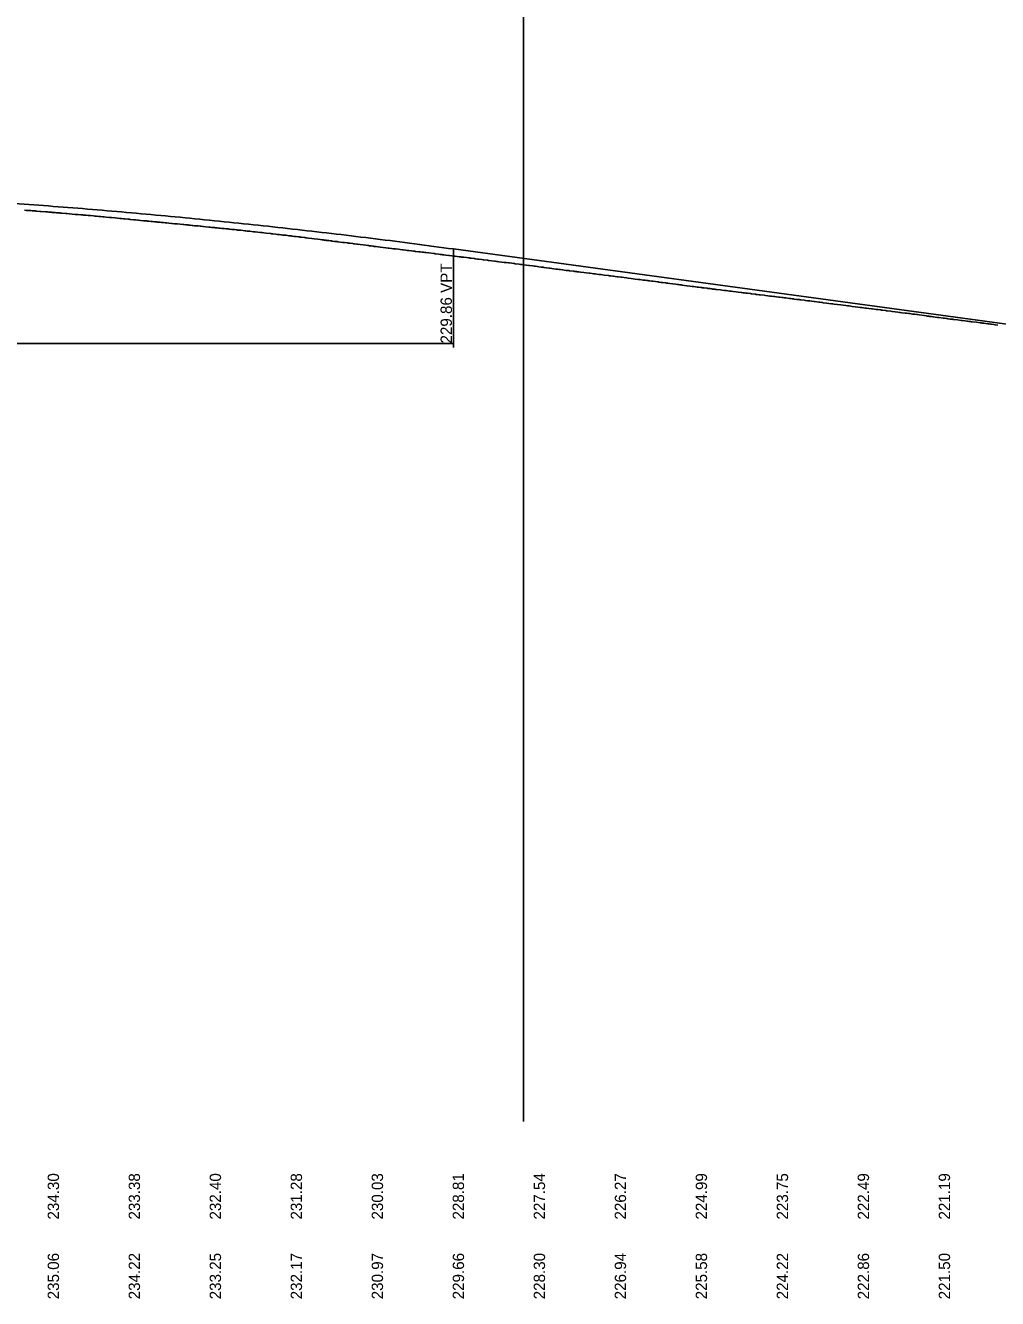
# Model space of a CAD drawing. Extents: x 1838386 to 1955906, y 719739 to 834437.
# Drawn here: x 1890591 to 1891191, y 825634 to 826420 of the extents above; entities that cross this region are included whole.
import ezdxf

# ---------------------------------------------------------------- set-up
doc = ezdxf.new("R2010")
doc.units = 0
for name, color, linetype in [('RD_DDB_Profile_EX', 7, 'Continuous'), ('RD_DDB_Profile_PR', 7, 'Continuous'), ('RD_DDB_StripGrade', 7, 'Continuous'), ('RD_DDB_VCLbl', 7, 'Continuous'), ('RD_Sketch1', 7, 'Continuous')]:
    doc.layers.add(name, color=color, linetype=linetype)

msp = doc.modelspace()

# ---------------------------------------------------------------- linework, layer by layer
at = {"layer": 'RD_DDB_Profile_EX'}
for points in [[(1890590.81, 826306.42), (1890592.08, 826306.29), (1890593.56, 826306.2), (1890594.18, 826306.16), (1890594.75, 826306.1), (1890595.54, 826306.02), (1890597.46, 826305.91), (1890597.94, 826305.87), (1890600.28, 826305.67), (1890601.13, 826305.6), (1890603.9, 826305.36), (1890604.35, 826305.32), (1890604.93, 826305.28), (1890605.81, 826305.2), (1890606.2, 826305.16), (1890607.18, 826305.09), (1890607.83, 826305.02), (1890608.71, 826304.97), (1890609.71, 826304.87), (1890610.45, 826304.81), (1890611.33, 826304.74), (1890612.52, 826304.65), (1890613.17, 826304.59), (1890613.74, 826304.54), (1890616.29, 826304.33), (1890616.97, 826304.27), (1890618.48, 826304.11), (1890620.11, 826304.01), (1890621.99, 826303.8), (1890622.39, 826303.78), (1890623.46, 826303.72), (1890623.95, 826303.68)], [(1890623.95, 826303.68), (1890625.44, 826303.51), (1890626.89, 826303.43), (1890627.24, 826303.4), (1890627.61, 826303.37), (1890627.92, 826303.33), (1890628.9, 826303.22), (1890630.1, 826303.13), (1890630.79, 826303.06), (1890631.54, 826303.01), (1890633.44, 826302.83), (1890634.25, 826302.74), (1890635.25, 826302.67), (1890636.61, 826302.54), (1890637.72, 826302.42), (1890639.11, 826302.32), (1890639.93, 826302.24), (1890641.2, 826302.09), (1890643.15, 826301.95), (1890644.19, 826301.86), (1890644.5, 826301.83), (1890646.76, 826301.61), (1890649.54, 826301.35), (1890650.02, 826301.3), (1890650.6, 826301.25), (1890651.86, 826301.1), (1890652.78, 826301.03), (1890654.47, 826300.87), (1890655.55, 826300.76), (1890656.05, 826300.72), (1890658.29, 826300.5), (1890658.8, 826300.44), (1890659.28, 826300.4), (1890660.63, 826300.24), (1890661.08, 826300.21), (1890662.42, 826300.1), (1890664.17, 826299.89), (1890665.65, 826299.78), (1890666.03, 826299.74), (1890666.6, 826299.67), (1890667.64, 826299.54), (1890668.98, 826299.45), (1890669.84, 826299.37), (1890671.11, 826299.22), (1890672.27, 826299.13), (1890672.92, 826299.06), (1890673.63, 826299), (1890674.58, 826298.89), (1890675.43, 826298.82), (1890676.47, 826298.7), (1890677.66, 826298.62), (1890678.13, 826298.57), (1890678.6, 826298.52), (1890679.95, 826298.36), (1890681.43, 826298.25), (1890681.88, 826298.21), (1890683.43, 826298.02), (1890685.22, 826297.89), (1890686.91, 826297.68), (1890688.76, 826297.54), (1890689.12, 826297.5), (1890690.4, 826297.35), (1890691.58, 826297.25), (1890692.3, 826297.17), (1890693.09, 826297.11), (1890694.24, 826296.99), (1890694.73, 826296.94), (1890695.78, 826296.81), (1890697, 826296.72), (1890697.92, 826296.63), (1890699.27, 826296.46), (1890699.76, 826296.43), (1890700.75, 826296.35), (1890701.24, 826296.3), (1890702.76, 826296.11), (1890704.63, 826295.98), (1890705.29, 826295.9), (1890706.26, 826295.77), (1890707.66, 826295.66), (1890708.1, 826295.62), (1890708.57, 826295.58), (1890709.75, 826295.43), (1890710.82, 826295.35), (1890711.63, 826295.26), (1890712.53, 826295.18), (1890713.28, 826295.09), (1890713.96, 826295.03), (1890715.16, 826294.89), (1890716.49, 826294.78), (1890717.11, 826294.72), (1890718.67, 826294.51), (1890720.43, 826294.37), (1890721.87, 826294.18), (1890722.18, 826294.13), (1890723.51, 826294.03), (1890724.34, 826293.95), (1890725.69, 826293.78), (1890726.71, 826293.69), (1890727.4, 826293.62), (1890728.24, 826293.53), (1890729.2, 826293.41)], [(1890729.2, 826293.41), (1890729.93, 826293.34), (1890732.16, 826293.11), (1890733.13, 826293), (1890736.34, 826292.66), (1890737.52, 826292.54), (1890738.45, 826292.43), (1890739.99, 826292.26), (1890742.74, 826291.93), (1890743.26, 826291.87), (1890743.98, 826291.79), (1890745.93, 826291.56), (1890746.79, 826291.45), (1890747.89, 826291.34), (1890749.09, 826291.2), (1890749.5, 826291.15), (1890750.31, 826291.04), (1890751.89, 826290.9), (1890752.2, 826290.86), (1890753.84, 826290.64), (1890755.03, 826290.52), (1890755.33, 826290.5), (1890755.89, 826290.43), (1890757.37, 826290.21), (1890758.5, 826290.1), (1890759.85, 826289.95), (1890760.56, 826289.85), (1890760.89, 826289.8), (1890761.69, 826289.71), (1890763.8, 826289.44), (1890764.42, 826289.36), (1890764.89, 826289.29), (1890766.08, 826289.14), (1890768.11, 826288.89), (1890769.66, 826288.65), (1890771.74, 826288.43), (1890773.18, 826288.23), (1890774.44, 826288.09), (1890775.03, 826288.02), (1890775.73, 826287.94), (1890776.7, 826287.8), (1890777.14, 826287.75), (1890777.54, 826287.71), (1890778.52, 826287.58), (1890779.67, 826287.47), (1890780.2, 826287.4), (1890780.63, 826287.35), (1890782.05, 826287.13), (1890782.66, 826287.07), (1890783.78, 826286.97), (1890784.11, 826286.93), (1890787.29, 826286.51), (1890787.68, 826286.46), (1890788.19, 826286.4), (1890790.21, 826286.13), (1890790.84, 826286.04), (1890791.71, 826285.95), (1890793.34, 826285.74), (1890793.72, 826285.69), (1890794.4, 826285.59), (1890795.8, 826285.44), (1890796.38, 826285.37), (1890797.92, 826285.14), (1890799.77, 826284.95), (1890801.46, 826284.7), (1890802.71, 826284.57), (1890803.15, 826284.51), (1890803.74, 826284.45), (1890804.77, 826284.32), (1890805.93, 826284.17), (1890806.7, 826284.05), (1890807.76, 826283.95), (1890809.08, 826283.79), (1890810.3, 826283.6), (1890812.06, 826283.42), (1890813.79, 826283.16), (1890815.19, 826283.02), (1890815.9, 826282.93), (1890817.34, 826282.73), (1890818.42, 826282.61), (1890819.04, 826282.53), (1890819.87, 826282.45), (1890821.62, 826282.24), (1890822.6, 826282.09), (1890824, 826281.95), (1890824.65, 826281.87), (1890826.15, 826281.66), (1890826.88, 826281.58), (1890827.69, 826281.5), (1890828.08, 826281.45), (1890829.69, 826281.23), (1890830.9, 826281.1), (1890831.4, 826281.04), (1890832.06, 826280.97), (1890832.41, 826280.93), (1890834.12, 826280.72), (1890834.96, 826280.6), (1890836.22, 826280.48), (1890836.72, 826280.41), (1890837.13, 826280.37), (1890837.93, 826280.25)], [(1890837.93, 826280.25), (1890838.5, 826280.17), (1890840.27, 826280), (1890843.46, 826279.59), (1890843.77, 826279.54), (1890844.28, 826279.49), (1890846.6, 826279.2), (1890847.35, 826279.1), (1890848.46, 826278.99), (1890849.08, 826278.91), (1890849.57, 826278.85), (1890850.87, 826278.66), (1890852.64, 826278.47), (1890853.19, 826278.4), (1890854.51, 826278.23), (1890856.17, 826278.01), (1890856.6, 826277.97), (1890857.91, 826277.79), (1890858.99, 826277.67), (1890859.71, 826277.57), (1890860.04, 826277.54), (1890860.69, 826277.47), (1890861.43, 826277.38), (1890861.95, 826277.31), (1890865.14, 826276.92), (1890865.57, 826276.86), (1890866.44, 826276.75), (1890868.56, 826276.47), (1890868.89, 826276.43), (1890870.29, 826276.24), (1890871.29, 826276.12), (1890873.04, 826275.9), (1890873.83, 826275.8), (1890874.39, 826275.73), (1890876.62, 826275.46), (1890877.15, 826275.4), (1890877.63, 826275.34), (1890879.14, 826275.11), (1890880.91, 826274.91), (1890881.27, 826274.87), (1890882.15, 826274.75), (1890882.68, 826274.68), (1890883.65, 826274.57), (1890885.43, 826274.36), (1890886.88, 826274.18), (1890887.67, 826274.06), (1890887.99, 826274.01), (1890889.59, 826273.85), (1890889.89, 826273.81), (1890891.53, 826273.59), (1890892.9, 826273.43), (1890893.2, 826273.4), (1890893.72, 826273.33), (1890896.14, 826273.03), (1890896.86, 826272.92), (1890897.94, 826272.8), (1890898.73, 826272.7), (1890899.11, 826272.65), (1890900.39, 826272.46), (1890902.15, 826272.26), (1890902.55, 826272.21), (1890904.25, 826271.99), (1890905.4, 826271.84), (1890905.73, 826271.79), (1890906.24, 826271.74), (1890907.46, 826271.58), (1890908.33, 826271.46), (1890909.78, 826271.27), (1890910.39, 826271.19), (1890910.99, 826271.11), (1890911.41, 826271.05), (1890914.62, 826270.63), (1890915.31, 826270.53), (1890916.32, 826270.38), (1890917.5, 826270.23), (1890918.82, 826270.06), (1890919.87, 826269.92), (1890920.83, 826269.8), (1890921.62, 826269.67), (1890922.89, 826269.53), (1890923.81, 826269.41), (1890925.17, 826269.22), (1890926.36, 826269.09), (1890926.7, 826269.05), (1890927.2, 826268.99), (1890929.93, 826268.64), (1890930.51, 826268.56), (1890931.41, 826268.46), (1890931.89, 826268.4), (1890932.26, 826268.35), (1890932.87, 826268.28), (1890934.04, 826268.11), (1890935.96, 826267.91), (1890937.41, 826267.73), (1890939.36, 826267.48), (1890939.72, 826267.44), (1890941.11, 826267.25), (1890942, 826267.14), (1890942.94, 826267.03), (1890944.02, 826266.9), (1890945.23, 826266.75)], [(1890945.23, 826266.75), (1890946.47, 826266.58), (1890948.47, 826266.35), (1890951.26, 826265.98), (1890951.77, 826265.9), (1890952.48, 826265.82), (1890953.99, 826265.63), (1890954.34, 826265.59), (1890955.32, 826265.45), (1890956.72, 826265.3), (1890957.27, 826265.23), (1890959.05, 826265.01), (1890959.52, 826264.95), (1890960.94, 826264.77), (1890962.41, 826264.56), (1890963.35, 826264.45), (1890965.26, 826264.21), (1890966.56, 826264.05), (1890967.76, 826263.87), (1890969.61, 826263.66), (1890970.58, 826263.53), (1890972.6, 826263.27), (1890973.08, 826263.2), (1890973.81, 826263.11), (1890974.84, 826262.97), (1890975.57, 826262.87), (1890976.1, 826262.8), (1890976.63, 826262.72), (1890978.07, 826262.56), (1890978.63, 826262.48), (1890980.17, 826262.27), (1890981.95, 826262.05), (1890982.33, 826262), (1890983.72, 826261.81), (1890984.67, 826261.69), (1890986.61, 826261.45), (1890987.16, 826261.38), (1890987.77, 826261.3), (1890989.05, 826261.11), (1890990.94, 826260.88), (1890992.68, 826260.66), (1890993.85, 826260.51), (1890994.39, 826260.43), (1890995.2, 826260.34), (1890996.14, 826260.2), (1890996.76, 826260.13), (1890998.21, 826259.94), (1890999.5, 826259.77), (1890999.89, 826259.72), (1891001.48, 826259.5), (1891002.81, 826259.34), (1891003.86, 826259.21), (1891005.91, 826258.95), (1891006.83, 826258.83), (1891008.19, 826258.68), (1891008.87, 826258.59), (1891009.26, 826258.53), (1891010.38, 826258.37), (1891012.17, 826258.17), (1891012.54, 826258.13), (1891013.95, 826257.94), (1891014.94, 826257.82), (1891015.73, 826257.71), (1891016.93, 826257.58), (1891017.5, 826257.51), (1891017.88, 826257.46), (1891020.46, 826257.15), (1891021.23, 826257.05), (1891022.85, 826256.84), (1891023.88, 826256.72), (1891025.84, 826256.47), (1891027.04, 826256.32), (1891028.18, 826256.16), (1891030.01, 826255.96), (1891031.37, 826255.79), (1891033.05, 826255.57), (1891033.52, 826255.51), (1891034.27, 826255.43), (1891035.29, 826255.29), (1891035.95, 826255.21), (1891037.08, 826255.05), (1891038.97, 826254.84), (1891039.58, 826254.77), (1891042.03, 826254.46), (1891042.45, 826254.4), (1891043.1, 826254.33), (1891044.21, 826254.18), (1891044.91, 826254.1), (1891047.42, 826253.81), (1891048.05, 826253.73), (1891049.55, 826253.52), (1891050.92, 826253.37), (1891051.86, 826253.26), (1891053.12, 826253.09), (1891053.48, 826253.05), (1891053.97, 826252.99), (1891054.91, 826252.86), (1891056.28, 826252.72), (1891057.01, 826252.63), (1891058.47, 826252.44), (1891059, 826252.38)], [(1891059, 826252.38), (1891059.89, 826252.28), (1891060.73, 826252.18), (1891063, 826251.88), (1891063.81, 826251.77), (1891064.53, 826251.69), (1891065.08, 826251.64), (1891065.59, 826251.58), (1891065.92, 826251.54), (1891067.39, 826251.33), (1891068.87, 826251.16), (1891069.59, 826251.07), (1891070.06, 826251.01), (1891071.96, 826250.76), (1891072.74, 826250.65), (1891073.98, 826250.51), (1891074.51, 826250.44), (1891074.83, 826250.4), (1891075.58, 826250.31), (1891076.63, 826250.18), (1891078.09, 826249.99), (1891078.42, 826249.95), (1891081.11, 826249.59), (1891081.67, 826249.51), (1891082.92, 826249.38), (1891083.44, 826249.32), (1891083.76, 826249.28), (1891085.74, 826249.02), (1891087.29, 826248.82), (1891088.79, 826248.61), (1891089.8, 826248.49), (1891090.6, 826248.37), (1891092.37, 826248.17), (1891092.68, 826248.13), (1891094.73, 826247.87), (1891096.19, 826247.68), (1891097.72, 826247.47), (1891098.7, 826247.35), (1891099.53, 826247.23), (1891100.85, 826247.08), (1891101.6, 826246.99), (1891103.48, 826246.76), (1891105.17, 826246.55), (1891106.66, 826246.35), (1891107.61, 826246.25), (1891108.74, 826246.09), (1891109.83, 826245.97), (1891110.5, 826245.88), (1891112.01, 826245.69), (1891113.81, 826245.46), (1891114.27, 826245.41), (1891116.51, 826245.12), (1891117.4, 826244.99), (1891118.84, 826244.83), (1891119.39, 826244.76), (1891119.8, 826244.71), (1891120.47, 826244.63), (1891122.41, 826244.38), (1891122.76, 826244.33), (1891123.3, 826244.27), (1891125.41, 826243.99), (1891126.34, 826243.85), (1891128.28, 826243.63), (1891129.91, 826243.4), (1891130.85, 826243.29), (1891131.23, 826243.25), (1891132.4, 826243.1), (1891134.27, 826242.85), (1891135.28, 826242.7), (1891136.38, 826242.58), (1891137.18, 826242.49), (1891138.87, 826242.27), (1891140.07, 826242.12), (1891141.5, 826241.94), (1891141.91, 826241.89), (1891143.08, 826241.74), (1891146.07, 826241.32), (1891147.43, 826241.1), (1891147.82, 826241.04), (1891148.95, 826240.89), (1891149.61, 826240.78), (1891150.69, 826240.68), (1891151.41, 826240.59), (1891151.85, 826240.54), (1891152.96, 826240.39), (1891154.3, 826240.22), (1891155.15, 826240.11), (1891157.83, 826239.76), (1891158.57, 826239.65), (1891159.78, 826239.51), (1891160.36, 826239.44), (1891160.71, 826239.39), (1891162.16, 826239.18), (1891163.62, 826239.01), (1891164.01, 826238.96), (1891164.45, 826238.91), (1891166.61, 826238.63), (1891168.94, 826238.35), (1891169.58, 826238.27), (1891171.12, 826238.05), (1891172.48, 826237.89)], [(1891172.48, 826237.89), (1891172.92, 826237.83), (1891173.65, 826237.75), (1891174.72, 826237.61), (1891175.36, 826237.53), (1891178.33, 826237.16), (1891180.59, 826236.85), (1891181.29, 826236.76), (1891181.89, 826236.67), (1891182.85, 826236.57), (1891184.23, 826236.4), (1891185.48, 826236.22), (1891186.12, 826236.15), (1891187.11, 826236.04), (1891187.55, 826235.99), (1891189.07, 826235.78), (1891190, 826235.67), (1891191.65, 826235.47)]]:
    msp.add_lwpolyline(points, dxfattribs=at)
at = {"layer": 'RD_DDB_Profile_PR'}
msp.add_line((1890855.58, 826282.42), (1891213.08, 826233.83), dxfattribs=at)
msp.add_spline([(1889650.58, 826274.06), (1889674.68, 826277.6), (1889698.78, 826281), (1889722.88, 826284.27), (1889746.98, 826287.4), (1889771.08, 826290.39), (1889795.18, 826293.24), (1889819.28, 826295.95), (1889843.38, 826298.53), (1889867.48, 826300.97), (1889891.58, 826303.27), (1889915.68, 826305.44), (1889939.78, 826307.47), (1889963.88, 826309.35), (1889987.98, 826311.11), (1890012.08, 826312.72), (1890036.18, 826314.19), (1890060.28, 826315.53), (1890084.38, 826316.73), (1890108.48, 826317.79), (1890132.58, 826318.72), (1890156.68, 826319.51), (1890180.78, 826320.16), (1890204.88, 826320.67), (1890228.98, 826321.04), (1890253.08, 826321.28), (1890277.18, 826321.38), (1890301.28, 826321.34), (1890325.38, 826321.16), (1890349.48, 826320.85), (1890373.58, 826320.39), (1890397.68, 826319.8), (1890421.78, 826319.07), (1890445.88, 826318.21), (1890469.98, 826317.21), (1890494.08, 826316.06), (1890518.18, 826314.79), (1890542.28, 826313.37), (1890566.38, 826311.81), (1890590.48, 826310.12), (1890614.58, 826308.29), (1890638.68, 826306.33), (1890662.78, 826304.22), (1890686.88, 826301.98), (1890710.98, 826299.6), (1890735.08, 826297.08), (1890759.18, 826294.42), (1890783.28, 826291.63), (1890807.38, 826288.7), (1890831.48, 826285.63), (1890855.58, 826282.42)], degree=3, dxfattribs=at)
at = {"layer": 'RD_DDB_VCLbl'}
for p, q in [((1890855.58, 826221.56), (1890855.58, 826282.42)), ((1889650.58, 826224.06), (1890855.58, 826224.06))]:
    msp.add_line(p, q, dxfattribs=at)
at = {"layer": 'RD_Sketch1'}
msp.add_line((1890898.8, 825743.65), (1890898.8, 827268.63), dxfattribs=at)

# ---------------------------------------------------------------- texts
at = {"layer": 'RD_DDB_StripGrade'}
for s, p in [('229.86 VPT', (1890854.58, 826224.06)), ('234.30', (1890612.08, 825683.11)), ('233.38', (1890662.08, 825683.11)), ('232.40', (1890712.08, 825683.11)), ('231.28', (1890762.08, 825683.11)), ('230.03', (1890812.08, 825683.11)), ('228.81', (1890862.08, 825683.11)), ('227.54', (1890912.08, 825683.11)), ('226.27', (1890962.08, 825683.11)), ('224.99', (1891012.08, 825683.11)), ('223.75', (1891062.08, 825683.11)), ('222.49', (1891112.08, 825683.11)), ('221.19', (1891162.08, 825683.11)), ('235.06', (1890612.08, 825633.86)), ('234.22', (1890662.08, 825633.86)), ('233.25', (1890712.08, 825633.86)), ('232.17', (1890762.08, 825633.86)), ('230.97', (1890812.08, 825633.86)), ('229.66', (1890862.08, 825633.86)), ('228.30', (1890912.08, 825633.86)), ('226.94', (1890962.08, 825633.86)), ('225.58', (1891012.08, 825633.86)), ('224.22', (1891062.08, 825633.86)), ('222.86', (1891112.08, 825633.86)), ('221.50', (1891162.08, 825633.86))]:
    msp.add_text(s, height=7, rotation=90, dxfattribs=at).set_placement(p)

doc.saveas('drawing.dxf')
